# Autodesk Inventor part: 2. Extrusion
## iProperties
Created: 2011-05
Part Number: 2. Extrusion
Document SubType Name: Modeling
Designer: Lorenz Humpel
Density: 1 g/cm^3
Author: Lorenz Humpel
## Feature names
1. Extrusion1
